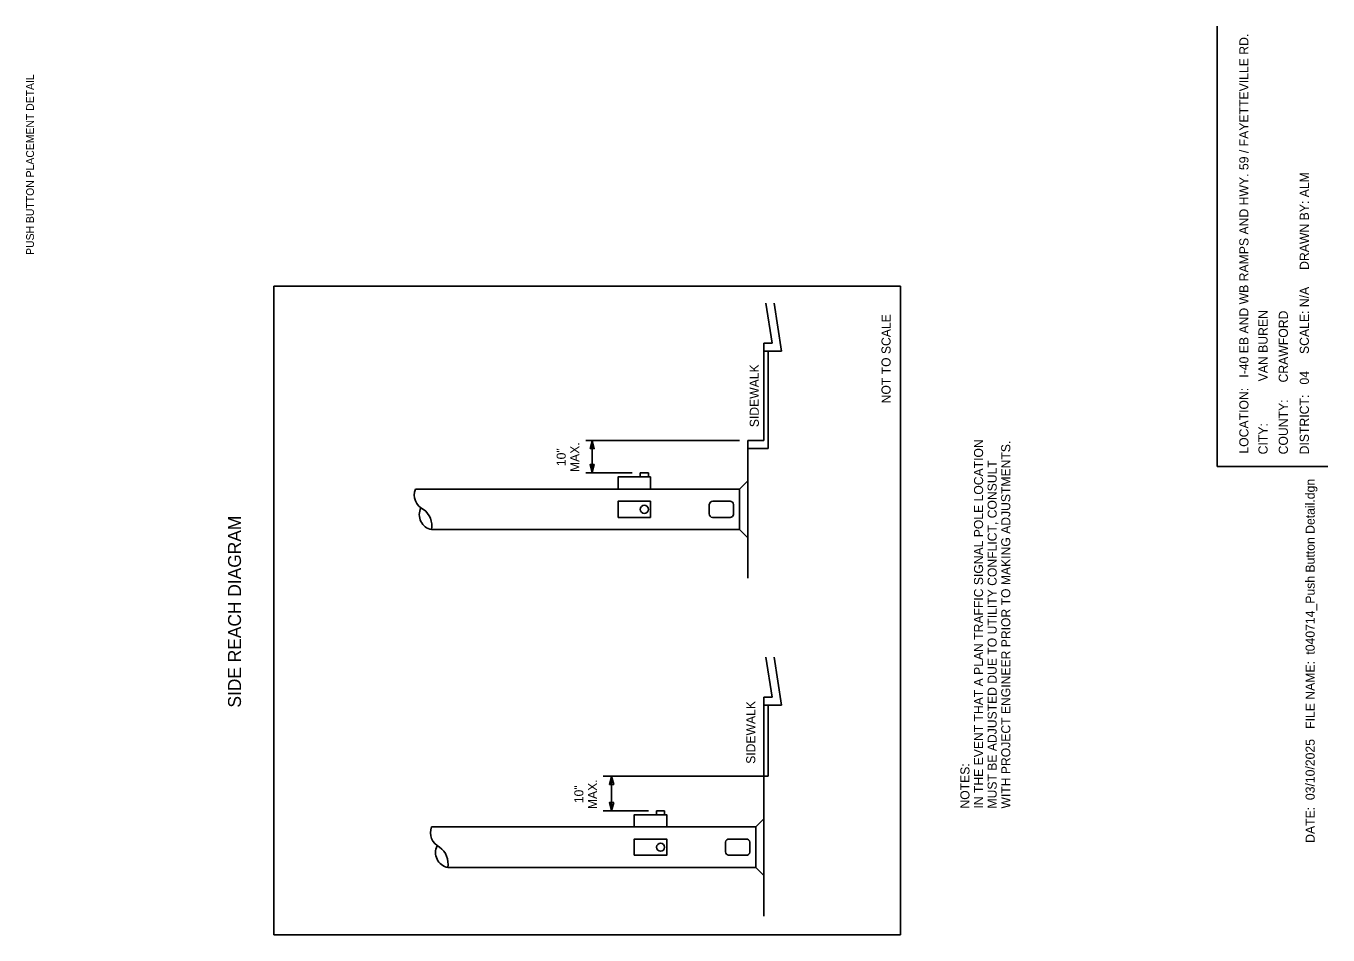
# Model space of a CAD drawing. Extents: x 610558 to 611161, y 419194 to 420064.
# Drawn here: x 610558 to 611161, y 419644 to 420064 of the extents above; entities that cross this region are included whole.
import ezdxf

# ---------------------------------------------------------------- set-up
doc = ezdxf.new("R2010")
doc.units = 0
for name, color, linetype in [('G-ANNO-TEXT', 7, 'Continuous'), ('Level 10', 7, 'Continuous'), ('Level 57', 7, 'Continuous')]:
    doc.layers.add(name, color=color, linetype=linetype)

msp = doc.modelspace()

# ---------------------------------------------------------------- linework, layer by layer
at = {"layer": 'Level 10'}
for p, q in [((610673.08, 419644.01), (610673.08, 419944.01)), ((610673.08, 419944.01), (610962.92, 419944.01)), ((610962.92, 419644.01), (610962.92, 419944.01)), ((610903.48, 419917.65), (610900.61, 419936.18)), ((610907.85, 419913.9), (610904.4, 419936.18)), ((610899.73, 419872.65), (610899.73, 419917.65)), ((610899.73, 419917.65), (610903.48, 419917.65)), ((610899.73, 419913.9), (610907.85, 419913.9)), ((610901.6, 419868.9), (610901.6, 419913.9)), ((610888.48, 419872.65), (610817.35, 419872.65)), ((610820.25, 419857.65), (610820.25, 419872.65)), ((610892.23, 419827.65), (610892.23, 419872.65)), ((610892.23, 419872.65), (610899.73, 419872.65)), ((610892.23, 419868.9), (610901.6, 419868.9)), ((610838.79, 419857.65), (610817.35, 419857.65)), ((610842.54, 419855.78), (610842.54, 419857.65)), ((610842.54, 419857.65), (610846.29, 419857.65)), ((610846.29, 419855.78), (610846.29, 419857.65)), ((610738.48, 419850.15), (610888.48, 419850.15)), ((610888.48, 419850.15), (610892.23, 419853.9)), ((610888.48, 419831.4), (610888.48, 419850.15)), ((610874.44, 419843.09), (610874.44, 419838.7)), ((610884.03, 419844.53), (610876.11, 419844.53)), ((610885.69, 419838.47), (610885.69, 419843.09)), ((610875.89, 419837.03), (610884.03, 419837.03)), ((610745.98, 419831.4), (610888.48, 419831.4)), ((610888.48, 419831.4), (610892.23, 419827.65)), ((610892.23, 419827.65), (610892.23, 419808.9)), ((610903.48, 419753.96), (610900.61, 419772.49)), ((610907.85, 419750.21), (610904.4, 419772.49)), ((610899.73, 419697.71), (610899.73, 419753.96)), ((610899.73, 419753.96), (610903.48, 419753.96)), ((610899.73, 419750.21), (610907.85, 419750.21)), ((610901.6, 419717.35), (610901.6, 419750.21)), ((610901.6, 419717.35), (610825.29, 419717.35)), ((610829.28, 419701.46), (610829.28, 419717.35)), ((610846.29, 419701.46), (610825.29, 419701.46)), ((610850.04, 419699.58), (610850.04, 419701.46)), ((610850.04, 419701.46), (610853.79, 419701.46)), ((610853.79, 419699.58), (610853.79, 419701.46)), ((610895.98, 419693.96), (610899.73, 419697.71)), ((610899.73, 419671.46), (610899.73, 419697.71)), ((610745.98, 419693.96), (610895.98, 419693.96)), ((610895.98, 419675.21), (610895.98, 419693.96)), ((610881.94, 419686.89), (610881.94, 419682.5)), ((610891.53, 419688.33), (610883.61, 419688.33)), ((610893.19, 419682.27), (610893.19, 419686.89)), ((610883.39, 419680.83), (610891.53, 419680.83)), ((610753.48, 419675.21), (610895.98, 419675.21)), ((610895.98, 419675.21), (610899.73, 419671.46)), ((610899.73, 419671.46), (610899.73, 419652.71)), ((610962.92, 419644.01), (610673.08, 419644.01))]:
    msp.add_line(p, q, dxfattribs=at)
for points in [[(610819.29, 419868.85), (610820.25, 419872.65), (610821.2, 419868.85)], [(610821.2, 419861.46), (610820.25, 419857.65), (610819.29, 419861.46)], [(610832.23, 419850.15), (610832.23, 419855.78), (610847.23, 419855.78), (610847.23, 419850.15)], [(610832.23, 419837.03), (610832.23, 419844.53), (610847.23, 419844.53), (610847.23, 419837.03)], [(610828.33, 419713.54), (610829.28, 419717.35), (610830.23, 419713.54)], [(610830.23, 419705.27), (610829.28, 419701.46), (610828.33, 419705.27)], [(610839.73, 419693.96), (610839.73, 419699.58), (610854.73, 419699.58), (610854.73, 419693.96)], [(610839.73, 419680.83), (610839.73, 419688.33), (610854.73, 419688.33), (610854.73, 419680.83)]]:
    msp.add_lwpolyline(points, close=True, dxfattribs=at)
for centre in [(610844.41, 419840.78), (610851.91, 419684.58)]:
    msp.add_circle(centre, 1.87, dxfattribs=at)
for centre, radius, start, end in [((610745.45, 419847.51), 7.46, 159.21251, 244.39031), ((610876.07, 419842.89), 1.64, 88.51448, 173.20082), ((610884.07, 419842.89), 1.64, 6.79918, 91.48552), ((610747.32, 419838.28), 7.01, 152.97974, 258.95702), ((610736.67, 419833.12), 9.46, 349.55802, 54.0448), ((610876.08, 419838.66), 1.64, 178.51448, 263.20082), ((610884.07, 419838.67), 1.64, 268.51448, 353.20082), ((610752.95, 419691.31), 7.46, 159.21251, 244.39031), ((610883.57, 419686.7), 1.64, 88.51448, 173.20082), ((610891.57, 419686.7), 1.64, 6.79918, 91.48552), ((610754.82, 419682.08), 7.01, 152.97974, 258.95702), ((610744.17, 419676.92), 9.46, 349.55802, 54.0448), ((610883.58, 419682.46), 1.64, 178.51448, 263.20082), ((610891.57, 419682.47), 1.64, 268.51448, 353.20082)]:
    msp.add_arc(centre, radius, start, end, dxfattribs=at)
at = {"layer": 'Level 57'}
for points in [[(611109.39, 420064.23), (611109.39, 419860.64)], [(611109.39, 419860.64), (611160.6, 419860.64)]]:
    msp.add_lwpolyline(points, dxfattribs=at)

# ---------------------------------------------------------------- texts
at = {"layer": 'G-ANNO-TEXT'}
msp.add_text('PUSH BUTTON PLACEMENT DETAIL', height=3.6, rotation=90, dxfattribs=at).set_placement((610562.07, 419958.43))
at = {"layer": 'Level 10'}
for s, height, p in [('LOCATION:   I-40 EB AND WB RAMPS AND HWY. 59 / FAYETTEVILLE RD.', 4.221, (611123.82, 419866.54)), ('DISTRICT:   04     SCALE: N/A     DRAWN BY: ALM', 4.221, (611151.77, 419866.19)), ('NOT TO SCALE', 4.2, (610958.3, 419889.79)), ('VAN BUREN', 4.221, (611132.67, 419899.96)), ('COUNTY:     CRAWFORD', 4.221, (611142.05, 419866.19)), ('SIDEWALK', 4.2, (610897.35, 419878.78)), ('CITY:       ', 4.221, (611132.67, 419866.19)), ('IN THE EVENT THAT A PLAN TRAFFIC SIGNAL POLE LOCATION ', 4.2, (611001.08, 419702.45)), ('10"', 4.2, (610808.03, 419860.77)), ('MAX.', 4.2, (610814.33, 419858.02)), ('WITH PROJECT ENGINEER PRIOR TO MAKING ADJUSTMENTS.', 4.2, (611013.68, 419702.45)), ('MUST BE ADJUSTED DUE TO UTILITY CONFLICT, CONSULT ', 4.2, (611007.38, 419702.45)), ('t040714_Push Button Detail.dgn', 4.221, (611154.46, 419773.59)), ('SIDE REACH DIAGRAM', 6, (610657.84, 419749.13)), ('DATE:  03/10/2025   FILE NAME: ', 4.221, (611154.46, 419686.59)), ('SIDEWALK', 4.2, (610895.71, 419723.13)), ('NOTES:', 4.2, (610994.78, 419702.45)), ('10"', 4.2, (610816.19, 419704.93)), ('MAX.', 4.2, (610822.49, 419702.18))]:
    msp.add_text(s, height=height, rotation=90, dxfattribs=at).set_placement(p)

doc.saveas('drawing.dxf')
